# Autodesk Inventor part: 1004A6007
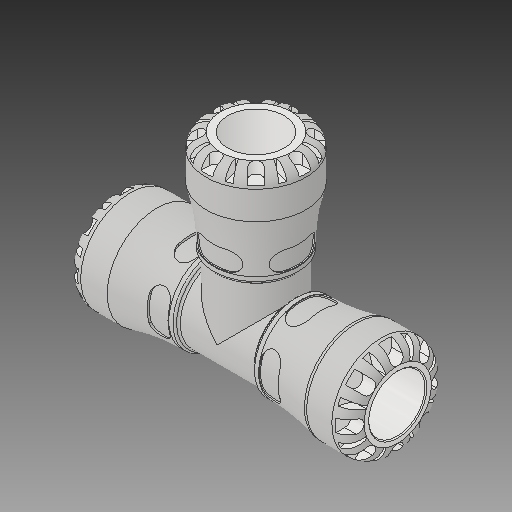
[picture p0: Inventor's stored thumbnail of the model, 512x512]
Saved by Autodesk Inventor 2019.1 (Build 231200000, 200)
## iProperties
Created: 2016-12
Part Number: 1004A6007
Material: Generic
Description: PLASSON TEE 3/4''IPS SERIES 1
Document SubType Name: Modeling
Designer: KIM
Mass: 664.223 g
Surface Area: 733.008 cm^2
Volume: 474.445 cm^3
Density: 1 g/cm^3
Appearance: Default
Author: KIM
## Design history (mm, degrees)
derived "1004A6.ipt"
feature "Solid1::1004A6.ipt"
tag "TaggingFeature1"
body "Solid1"
other parameters: "d1" = 20.16252, "d2" = 26.6, "d3" = 31.6975, "d4" = 46.99, "d8" = 39.9415, "d13" = 6.117, "d14" = 6.117, "d15" = 0, "d17" = 360 deg, "d19" = 8 deg, "d20" = 0.532, "d21" = 0.532, "d22" = 8 deg, "d24" = 0, "d26" = 360 deg, "d33" = 4.699, "d43" = 36.6522, "d51" = 0.4699, "d54" = 9.31, "d55" = 5.852, "d57" = 10.77216, "d58" = 0, "d74" = 0, "d78" = 48.006, "d79" = 36.6522, "d80" = 133.858, "d82" = 0.532, "d115" = 360 deg, "d139" = 6.117, "d140" = 0, "d142" = 360 deg, "d207" = 90 deg, "d209" = 20.16252, "d210" = 26.6, "d211" = 33.25, "d212" = 46.99, "d213" = 39.9415, "d215" = 36.6522, "d216" = 2.21667, "d217" = 48.006, "d225" = 77.978, "d226" = 48.006, "d228" = 7.9135, "d229" = 5.496, "d233" = 5.496, "d234" = 0, "d236" = 360 deg, "d238" = 8 deg, "d239" = 8 deg, "d240" = 0.532, "d241" = 0.532, "d243" = 0, "d245" = 360 deg, "d247" = 0.9398, "d248" = 2.88036, "d249" = 2.88036, "d250" = 7.9135, "d252" = 9.31, "d253" = 6.118, "d254" = 10.77216, "d255" = 0, "d257" = 360 deg, "d259" = 0.532, "d261" = 0, "d262" = 0.9398, "d264" = 0, "d266" = 0, "d268" = 21.28, "d_" = 26.6, "E_" = 46.99, "l_" = 48.006, "A_" = 77.978, "H_" = 133.858, "d9" = 7.64625, "d11" = 46.99, "d12" = 31.6975, "d230" = 46.99, "d231" = 33.25, "d232" = 6.87
